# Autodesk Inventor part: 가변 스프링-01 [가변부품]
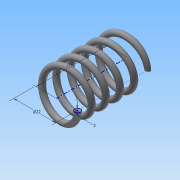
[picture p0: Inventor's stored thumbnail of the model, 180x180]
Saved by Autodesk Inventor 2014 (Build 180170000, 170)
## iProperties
Created: 2015-09
Part Number: 가변 스프링-01 [가변부품]
Material: 강철, 탄소
Document SubType Name: Modeling
Designer: study
Density: 7.87 g/cm^3
Appearance: 반연마
Mass: 18.8111 g
Surface Area: 32.4633 cm^2
Volume: 2.39023 cm^3
Author: study
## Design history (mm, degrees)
sketch "스케치1"
  geometry: L1 (0, 0)-(11, 0); L2 (11, 0)-(11, 28.893); L3 (11, 28.893)-(0, 28.893); L4 (0, 28.893)-(0, 0); C1 r 1.5 at (11, 0)
  constraints: 8 end point, 2 parallel, 1 centre point, 1 coincident, 1 horizontal, 1 perpendicular
  dimensions: "d0" = 28.89259 distance of L3.end L1.start (derived); "d1" = 22 diameter of L2 L4; "d2" = 3 diameter of C1
feature "코일1" sketch "스케치1" pitch "d3" = 10; turns "d5" = 5; dims "d4" = 28.89259 (= d0), "d6" = 0, angle "d7" = 90 deg, angle "d8" = 90 deg, "d9" = 0, "d10" = 0
sketch "스케치2"
  geometry: L1 (-12.5, 0)-(-9.5, 0) reference; 1 further point
  constraints: 1 horizontal alignment
extrude "돌출1" cut sketch "스케치2" distance "d11" = 10; taper "d12" = 0 deg
node "작업 평면1"
sketch "스케치3"
  geometry: L1 (-9.5, 0)-(-12.5, 0) reference; 1 further point
  constraints: 1 horizontal alignment
extrude "돌출2" cut sketch "스케치3" distance "d14" = 10; taper "d15" = 0 deg
node "솔리드1"
node "절단 모서리 투영1"
node "절단 모서리 투영2"
other parameters: "d13" = 28.89259 (= d0)
